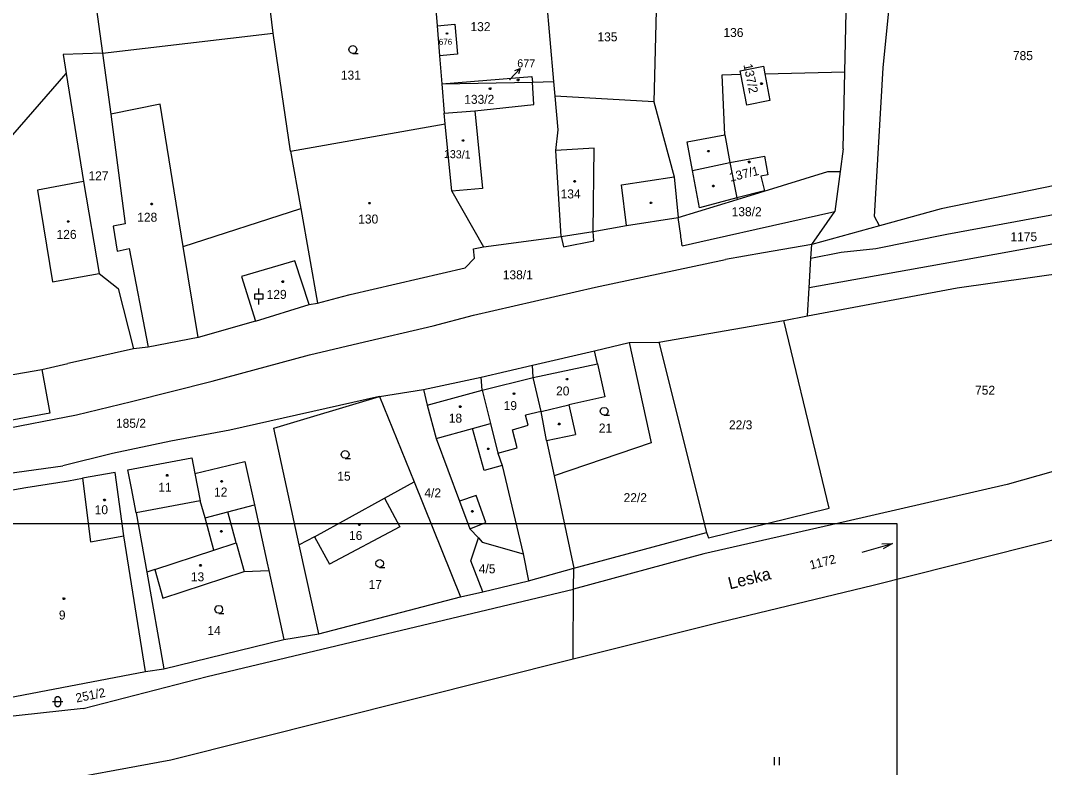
# Model space of a CAD drawing. Extents: x -812394 to -807601, y -1013097 to -1009266.
# Drawn here: x -809612.2 to -809418.3, y -1010813 to -1010671.6 of the extents above; entities that cross this region are included whole.
import ezdxf

# ---------------------------------------------------------------- set-up
doc = ezdxf.new("R2010")
doc.units = 0
for name, color, linetype in [('Default', 7, 'Continuous'), ('KN_HRANICE', 7, 'Continuous'), ('KN_KULTURY', 7, 'Continuous'), ('KN_PARCELY', 7, 'Continuous'), ('KN_SLUCKY', 7, 'Continuous'), ('LEGENDA', 7, 'Continuous')]:
    doc.layers.add(name, color=color, linetype=linetype)

# ---------------------------------------------------------------- blocks, each defined once
blk = doc.blocks.new('10292')
at = {"layer": 'Default'}
blk.add_line((0, 3), (0, 0), dxfattribs=at)
blk.add_lwpolyline([(-0.5, 2), (0, 3), (0.5, 2)], dxfattribs=at)
blk = doc.blocks.new('304')
at = {"layer": 'Default'}
blk.add_lwpolyline([(0, 0), (-0.38, 0.1), (-0.65, 0.37), (-0.75, 0.74), (-0.65, 1.11), (-0.38, 1.38), (-0.01, 1.48), (0.36, 1.38), (0.63, 1.11), (0.73, 0.73), (0.63, 0.35), (0.36, 0.08), (-0.02, -0.02), (0.98, -0.02)], dxfattribs=at)
blk = doc.blocks.new('306')
at = {"layer": 'Default'}
for p, q in [((-0.5, 1.5), (-0.5, 0)), ((0.5, 0), (0.5, 1.5))]:
    blk.add_line(p, q, dxfattribs=at)
blk = doc.blocks.new('316')
at = {"layer": 'Default'}
for points in [[(-0.5, 1.5), (-0.4, 1.79), (-0.15, 1.97), (0.16, 1.97), (0.41, 1.79), (0.51, 1.5), (0.51, 0.5), (0.41, 0.21), (0.16, 0.03), (-0.15, 0.03), (-0.4, 0.21), (-0.5, 0.5), (-0.5, 1.5)], [(-1, 1), (0.27, 1), (1, 1)]]:
    blk.add_lwpolyline(points, dxfattribs=at)
blk = doc.blocks.new('NAHRADNI_SYMBOL')
at = {"layer": 'Default'}
blk.add_lwpolyline([(0.09, 0.15), (0.18, 0), (0.09, -0.15), (-0.09, -0.15), (-0.18, 0), (-0.09, 0.15), (0.09, 0.15)], dxfattribs=at)
blk = doc.blocks.new('802')
at = {"layer": 'Default'}
blk.add_line((-3, 0), (3, 0), dxfattribs=at)
blk.add_lwpolyline([(1, 0.5), (3, 0), (1, -0.5)], dxfattribs=at)
blk = doc.blocks.new('318')
at = {"layer": 'Default'}
blk.add_line((0, 2), (0, 3), dxfattribs=at)
blk.add_lwpolyline([(0, 0), (0, 1), (-0.75, 1), (-0.75, 2), (0, 2), (0.75, 2), (0.75, 1), (0, 1)], dxfattribs=at)
blk = doc.blocks.new('402')
at = {"layer": 'Default'}
blk.add_lwpolyline([(0.09, 0.15), (0.18, 0), (0.09, -0.15), (-0.09, -0.15), (-0.18, 0), (-0.09, 0.15), (0.09, 0.15)], dxfattribs=at)

msp = doc.modelspace()

# ---------------------------------------------------------------- linework, layer by layer
at = {"layer": 'KN_HRANICE'}
for p, q in [((-809448.82, -1010680.59), (-809445.9, -1010650.77)), ((-809511.21, -1010683.19), (-809513.45, -1010657.55)), ((-809491.57, -1010658.3), (-809492.27, -1010687)), ((-809534.45, -1010658.78), (-809533.33, -1010672.61)), ((-809564.36, -1010674), (-809565.97, -1010661.03)), ((-809456.08, -1010681.32), (-809455.72, -1010664.14)), ((-809598.46, -1010664.88), (-809596.67, -1010677.83)), ((-809561.08, -1010696.34), (-809564.36, -1010674)), ((-809533.33, -1010672.61), (-809532.87, -1010678.29)), ((-809596.67, -1010677.83), (-809604.12, -1010678.05)), ((-809604.12, -1010678.05), (-809603.55, -1010681.64)), ((-809596.67, -1010677.83), (-809595.14, -1010689.36)), ((-809532.87, -1010678.29), (-809532.44, -1010683.62)), ((-809603.55, -1010681.64), (-809600.29, -1010702.1)), ((-809479.37, -1010681.9), (-809475.82, -1010681.81)), ((-809478.82, -1010693.3), (-809479.37, -1010681.9)), ((-809475.94, -1010681.16), (-809471.53, -1010680.26)), ((-809475.82, -1010681.81), (-809475.94, -1010681.16)), ((-809474.7, -1010687.64), (-809475.82, -1010681.81)), ((-809471.53, -1010680.26), (-809471.26, -1010681.7)), ((-809471.26, -1010681.7), (-809456.08, -1010681.32)), ((-809471.26, -1010681.7), (-809470.29, -1010686.8)), ((-809456.4, -1010695.91), (-809456.08, -1010681.32)), ((-809450.49, -1010708.71), (-809448.82, -1010680.59)), ((-809532.44, -1010683.62), (-809515.29, -1010683.27)), ((-809532.44, -1010683.62), (-809531.99, -1010689.19)), ((-809515.29, -1010683.27), (-809511.21, -1010683.19)), ((-809510.97, -1010685.95), (-809511.21, -1010683.19)), ((-809492.27, -1010687), (-809510.97, -1010685.95)), ((-809510.41, -1010692.32), (-809510.97, -1010685.95)), ((-809492.27, -1010687), (-809488.44, -1010701.23)), ((-809470.29, -1010686.8), (-809474.7, -1010687.64)), ((-809595.14, -1010689.36), (-809592.38, -1010710.12)), ((-809531.99, -1010689.19), (-809526.16, -1010688.74)), ((-809531.79, -1010691.19), (-809531.99, -1010689.19)), ((-809561.08, -1010696.34), (-809531.79, -1010691.19)), ((-809530.54, -1010703.91), (-809531.79, -1010691.19)), ((-809510.85, -1010696.24), (-809510.41, -1010692.32)), ((-809485.94, -1010694.61), (-809478.82, -1010693.3)), ((-809484.96, -1010700.01), (-809485.94, -1010694.61)), ((-809561.08, -1010696.34), (-809559.16, -1010707.24)), ((-809509.86, -1010712.52), (-809510.85, -1010696.24)), ((-809456.4, -1010695.91), (-809456.99, -1010700.24)), ((-809488.44, -1010701.23), (-809487.68, -1010708.94)), ((-809483.66, -1010707.09), (-809484.96, -1010700.01)), ((-809476.51, -1010705.51), (-809459.32, -1010700.23)), ((-809459.32, -1010700.23), (-809456.99, -1010700.24)), ((-809456.99, -1010700.24), (-809458, -1010707.77)), ((-809600.29, -1010702.1), (-809597.34, -1010719.54)), ((-809413.39, -1010702.26), (-809437.86, -1010707.26)), ((-809530.54, -1010703.91), (-809524.53, -1010714.47)), ((-809476.56, -1010705.21), (-809483.66, -1010707.09)), ((-809476.56, -1010705.21), (-809476.51, -1010705.51)), ((-809487.68, -1010708.94), (-809476.51, -1010705.51)), ((-809581.39, -1010714.41), (-809559.16, -1010707.24)), ((-809559.16, -1010707.24), (-809556, -1010725.11)), ((-809497.45, -1010710.44), (-809487.68, -1010708.94)), ((-809487.2, -1010712.35), (-809487.68, -1010708.94)), ((-809481.63, -1010713.11), (-809458, -1010707.77)), ((-809462.39, -1010714.03), (-809458, -1010707.77)), ((-809449.57, -1010710.49), (-809450.49, -1010708.71)), ((-809437.86, -1010707.26), (-809449.57, -1010710.49)), ((-809592.38, -1010710.12), (-809594.66, -1010710.54)), ((-809594.66, -1010710.54), (-809593.93, -1010715.27)), ((-809503.76, -1010711.54), (-809497.45, -1010710.44)), ((-809449.57, -1010710.49), (-809462.39, -1010714.03)), ((-809524.53, -1010714.47), (-809509.86, -1010712.52)), ((-809509.86, -1010712.52), (-809509.39, -1010714.47)), ((-809503.65, -1010713.32), (-809503.76, -1010711.54)), ((-809487.15, -1010712.67), (-809487.2, -1010712.35)), ((-809487.06, -1010713.28), (-809487.15, -1010712.67)), ((-809593.93, -1010715.27), (-809591.65, -1010714.79)), ((-809591.65, -1010714.79), (-809588.06, -1010733.47)), ((-809578.59, -1010731.65), (-809581.39, -1010714.41)), ((-809526.41, -1010714.85), (-809524.53, -1010714.47)), ((-809526.26, -1010716.6), (-809526.41, -1010714.85)), ((-809509.39, -1010714.47), (-809503.65, -1010713.32)), ((-809486.99, -1010713.83), (-809487.06, -1010713.28)), ((-809486.92, -1010714.3), (-809486.99, -1010713.83)), ((-809486.92, -1010714.3), (-809481.63, -1010713.11)), ((-809462.39, -1010714.03), (-809471.53, -1010715.63)), ((-809462.54, -1010716.59), (-809462.39, -1010714.03)), ((-809528.01, -1010718.45), (-809526.26, -1010716.6)), ((-809503.35, -1010722.13), (-809478.73, -1010716.9)), ((-809471.53, -1010715.63), (-809478.73, -1010716.9)), ((-809462.86, -1010722.22), (-809462.54, -1010716.59)), ((-809434.83, -1010722.26), (-809386.46, -1010715.35)), ((-809549.8, -1010723.5), (-809528.01, -1010718.45)), ((-809597.34, -1010719.54), (-809593.76, -1010722.34)), ((-809593.76, -1010722.34), (-809590.8, -1010733.81)), ((-809526.46, -1010727.38), (-809503.35, -1010722.13)), ((-809463.16, -1010727.52), (-809462.86, -1010722.22)), ((-809463.16, -1010727.52), (-809434.83, -1010722.26)), ((-809556, -1010725.11), (-809551.26, -1010723.86)), ((-809551.26, -1010723.86), (-809549.8, -1010723.5)), ((-809567.73, -1010728.55), (-809557.57, -1010725.36)), ((-809557.57, -1010725.36), (-809556, -1010725.11)), ((-809567.73, -1010728.55), (-809578.59, -1010731.65)), ((-809534.09, -1010729.46), (-809526.46, -1010727.38)), ((-809491.31, -1010732.5), (-809467.68, -1010728.42)), ((-809467.68, -1010728.42), (-809463.16, -1010727.52)), ((-809548.16, -1010732.72), (-809534.09, -1010729.46)), ((-809578.59, -1010731.65), (-809588.06, -1010733.47)), ((-809590.8, -1010733.81), (-809601.82, -1010736.22)), ((-809588.06, -1010733.47), (-809590.8, -1010733.81)), ((-809557.49, -1010734.93), (-809548.16, -1010732.72)), ((-809515.24, -1010736.89), (-809503.51, -1010734.14)), ((-809503.51, -1010734.14), (-809496.94, -1010732.6)), ((-809502.98, -1010736.65), (-809503.51, -1010734.14)), ((-809496.94, -1010732.6), (-809491.31, -1010732.5)), ((-809496.94, -1010732.6), (-809492.77, -1010751.6)), ((-809491.31, -1010732.5), (-809482.31, -1010768.54)), ((-809601.82, -1010736.22), (-809603.28, -1010736.54)), ((-809575.93, -1010739.9), (-809557.49, -1010734.93)), ((-809618.66, -1010739.51), (-809608.17, -1010737.7)), ((-809608.17, -1010737.7), (-809603.28, -1010736.54)), ((-809608.17, -1010737.7), (-809606.66, -1010745.99)), ((-809524.96, -1010739.16), (-809515.24, -1010736.89)), ((-809515.12, -1010739.21), (-809515.24, -1010736.89)), ((-809502.98, -1010736.65), (-809501.59, -1010742.84)), ((-809591.21, -1010743.76), (-809575.93, -1010739.9)), ((-809535.88, -1010741.49), (-809524.96, -1010739.16)), ((-809524.82, -1010741.63), (-809524.96, -1010739.16)), ((-809513.6, -1010745.64), (-809515.12, -1010739.21)), ((-809544.23, -1010742.79), (-809535.88, -1010741.49)), ((-809535.88, -1010741.49), (-809535.22, -1010744.44)), ((-809524.82, -1010741.63), (-809523.2, -1010747.95)), ((-809601.6, -1010746.29), (-809591.21, -1010743.76)), ((-809544.23, -1010742.79), (-809572.56, -1010749.19)), ((-809564.25, -1010748.81), (-809544.23, -1010742.79)), ((-809544.23, -1010742.79), (-809537.7, -1010758.97)), ((-809501.59, -1010742.84), (-809508.37, -1010744.41)), ((-809606.66, -1010745.99), (-809626.64, -1010749.55)), ((-809535.22, -1010744.44), (-809533.52, -1010750.77)), ((-809512.59, -1010751.13), (-809513.6, -1010745.64)), ((-809508.37, -1010744.41), (-809507.14, -1010750.01)), ((-809621.25, -1010750.05), (-809601.6, -1010746.29)), ((-809572.56, -1010749.19), (-809583.73, -1010751.27)), ((-809559.42, -1010770.87), (-809564.25, -1010748.81)), ((-809523.2, -1010747.95), (-809521.85, -1010753.55)), ((-809583.73, -1010751.27), (-809594.82, -1010753.62)), ((-809533.52, -1010750.77), (-809529.09, -1010762.64)), ((-809512.59, -1010751.13), (-809507.14, -1010750.01)), ((-809512.59, -1010751.13), (-809511.16, -1010757.85)), ((-809492.77, -1010751.6), (-809511.16, -1010757.85)), ((-809594.82, -1010753.62), (-809604.22, -1010755.92)), ((-809521.85, -1010753.55), (-809521.03, -1010755.88)), ((-809591.91, -1010756.66), (-809579.76, -1010754.43)), ((-809579.76, -1010754.43), (-809579.19, -1010757.38)), ((-809579.19, -1010757.38), (-809569.76, -1010755.12)), ((-809569.76, -1010755.12), (-809567.94, -1010763.34)), ((-809619.48, -1010758), (-809604.22, -1010755.92)), ((-809594.29, -1010757.19), (-809600.5, -1010758.29)), ((-809592.64, -1010769.19), (-809594.29, -1010757.19)), ((-809591.2, -1010760.14), (-809591.91, -1010756.66)), ((-809579.19, -1010757.38), (-809578.18, -1010762.54)), ((-809521.03, -1010755.88), (-809517.06, -1010772.62)), ((-809611.19, -1010760.06), (-809603.15, -1010758.78)), ((-809603.15, -1010758.78), (-809600.5, -1010758.29)), ((-809600.5, -1010758.29), (-809598.99, -1010770.33)), ((-809543.29, -1010762.05), (-809537.7, -1010758.97)), ((-809537.7, -1010758.97), (-809528.91, -1010780.74)), ((-809511.16, -1010757.85), (-809507.45, -1010775.29)), ((-809619.76, -1010761.5), (-809611.19, -1010760.06)), ((-809590.34, -1010764.82), (-809591.2, -1010760.14)), ((-809577.28, -1010765.78), (-809578.18, -1010762.54)), ((-809572.99, -1010764.66), (-809567.94, -1010763.34)), ((-809567.94, -1010763.34), (-809565.5, -1010774.33)), ((-809556.56, -1010769.35), (-809543.29, -1010762.05)), ((-809543.29, -1010762.05), (-809540.4, -1010767.48)), ((-809529.09, -1010762.64), (-809527.15, -1010767.85)), ((-809590.34, -1010764.82), (-809588.33, -1010776.05)), ((-809577.28, -1010765.78), (-809572.99, -1010764.66)), ((-809481.91, -1010769.54), (-809459.07, -1010763.94)), ((-809575.59, -1010771.87), (-809577.28, -1010765.78)), ((-809598.99, -1010770.33), (-809592.64, -1010769.19)), ((-809588.54, -1010794.9), (-809592.64, -1010769.19)), ((-809540.4, -1010767.48), (-809553.7, -1010774.56)), ((-809527.15, -1010767.85), (-809525.51, -1010769.54)), ((-809507.45, -1010775.29), (-809482.31, -1010768.54)), ((-809482.31, -1010768.54), (-809481.91, -1010769.54)), ((-809450.75, -1010778.5), (-809413.92, -1010769.26)), ((-809556.56, -1010769.35), (-809559.42, -1010770.87)), ((-809555.73, -1010787.74), (-809559.42, -1010770.87)), ((-809556.56, -1010769.35), (-809553.7, -1010774.56)), ((-809526.96, -1010773.94), (-809525.51, -1010769.54)), ((-809525.51, -1010769.54), (-809524.78, -1010770.4)), ((-809524.78, -1010770.4), (-809517.06, -1010772.62)), ((-809586.77, -1010775.53), (-809575.59, -1010771.87)), ((-809517.06, -1010772.62), (-809516.02, -1010777.68)), ((-809565.5, -1010774.33), (-809565.19, -1010775.74)), ((-809524.66, -1010779.77), (-809526.96, -1010773.94)), ((-809586.77, -1010775.53), (-809588.33, -1010776.05)), ((-809588.33, -1010776.05), (-809585.11, -1010794.39)), ((-809586.77, -1010775.53), (-809585.25, -1010781)), ((-809585.25, -1010781), (-809569.85, -1010775.96)), ((-809569.85, -1010775.96), (-809565.19, -1010775.74)), ((-809565.19, -1010775.74), (-809562.33, -1010788.78)), ((-809516.02, -1010777.68), (-809507.45, -1010775.29)), ((-809507.48, -1010779.27), (-809507.45, -1010775.29)), ((-809524.66, -1010779.77), (-809516.02, -1010777.68)), ((-809479.79, -1010785.54), (-809450.75, -1010778.5)), ((-809576.87, -1010795.8), (-809507.48, -1010779.27)), ((-809555.73, -1010787.74), (-809528.91, -1010780.74)), ((-809528.91, -1010780.74), (-809524.66, -1010779.77)), ((-809507.51, -1010783.2), (-809507.48, -1010779.27)), ((-809507.54, -1010787.61), (-809507.51, -1010783.2)), ((-809507.57, -1010792.49), (-809479.79, -1010785.54)), ((-809562.33, -1010788.78), (-809555.73, -1010787.74)), ((-809507.57, -1010792.49), (-809507.54, -1010787.61)), ((-809585.11, -1010794.39), (-809562.33, -1010788.78)), ((-809583.77, -1010811.56), (-809507.57, -1010792.49)), ((-809588.54, -1010794.9), (-809585.11, -1010794.39)), ((-809615.96, -1010800.09), (-809588.54, -1010794.9)), ((-809600.38, -1010801.89), (-809576.87, -1010795.8)), ((-809600.38, -1010801.89), (-809643.49, -1010806.47)), ((-809609.07, -1010816.23), (-809583.77, -1010811.56))]:
    msp.add_line(p, q, dxfattribs=at)
for points in [[(-809533.33, -1010672.61), (-809529.94, -1010672.33), (-809529.46, -1010677.99), (-809532.87, -1010678.29)], [(-809623.13, -1010728.35), (-809625.78, -1010708.61), (-809623.83, -1010704.87), (-809603.55, -1010681.64)], [(-809532.44, -1010683.62), (-809515.36, -1010682.23), (-809515.29, -1010683.27)], [(-809526.16, -1010688.74), (-809514.99, -1010687.55), (-809515.29, -1010683.27)], [(-809386.86, -1010717.18), (-809390.64, -1010734.74), (-809392.82, -1010743.13), (-809395.75, -1010747.43), (-809400.98, -1010751.89), (-809410.38, -1010755.21), (-809425.36, -1010759.45), (-809455.87, -1010766.45), (-809482.83, -1010772.6), (-809507.48, -1010779.27)], [(-809459.07, -1010763.94), (-809461.16, -1010755.31), (-809467.68, -1010728.42)]]:
    msp.add_lwpolyline(points, dxfattribs=at)
at = {"layer": 'KN_SLUCKY'}
for p, q in [((-809596.67, -1010677.83), (-809564.36, -1010674)), ((-809585.78, -1010687.46), (-809595.14, -1010689.36)), ((-809581.39, -1010714.41), (-809585.78, -1010687.46)), ((-809526.16, -1010688.74), (-809524.76, -1010703.42)), ((-809478.82, -1010693.3), (-809477.86, -1010698.52)), ((-809503.61, -1010695.79), (-809510.85, -1010696.24)), ((-809503.76, -1010711.54), (-809503.61, -1010695.79)), ((-809477.86, -1010698.52), (-809471.32, -1010697.32)), ((-809471.32, -1010697.32), (-809470.68, -1010700.85)), ((-809484.96, -1010700.01), (-809477.86, -1010698.52)), ((-809477.86, -1010698.52), (-809476.56, -1010705.21)), ((-809498.4, -1010702.75), (-809488.44, -1010701.23)), ((-809470.68, -1010700.85), (-809472.02, -1010701.1)), ((-809472.02, -1010701.1), (-809471.31, -1010703.88)), ((-809600.29, -1010702.1), (-809609, -1010703.76)), ((-809497.45, -1010710.44), (-809498.4, -1010702.75)), ((-809609, -1010703.76), (-809606.14, -1010721.1)), ((-809524.76, -1010703.42), (-809530.54, -1010703.91)), ((-809471.31, -1010703.88), (-809476.56, -1010705.21)), ((-809509.86, -1010712.52), (-809503.76, -1010711.54)), ((-809560.3, -1010717.14), (-809570.39, -1010720.06)), ((-809557.57, -1010725.36), (-809560.3, -1010717.14)), ((-809606.14, -1010721.1), (-809597.34, -1010719.54)), ((-809570.39, -1010720.06), (-809567.73, -1010728.55)), ((-809515.12, -1010739.21), (-809502.98, -1010736.65)), ((-809524.82, -1010741.63), (-809515.12, -1010739.21)), ((-809535.22, -1010744.44), (-809524.82, -1010741.63)), ((-809513.6, -1010745.64), (-809516.56, -1010746.35)), ((-809513.6, -1010745.64), (-809508.37, -1010744.41)), ((-809516.09, -1010748.24), (-809516.56, -1010746.35)), ((-809533.52, -1010750.77), (-809526.63, -1010748.89)), ((-809526.63, -1010748.89), (-809523.2, -1010747.95)), ((-809524.42, -1010756.83), (-809526.63, -1010748.89)), ((-809519.06, -1010749.09), (-809516.09, -1010748.24)), ((-809518.14, -1010752.55), (-809519.06, -1010749.09)), ((-809521.85, -1010753.55), (-809518.14, -1010752.55)), ((-809521.03, -1010755.88), (-809524.42, -1010756.83)), ((-809525.94, -1010761.52), (-809529.09, -1010762.64)), ((-809524.07, -1010766.63), (-809525.94, -1010761.52)), ((-809578.18, -1010762.54), (-809590.34, -1010764.82)), ((-809571.37, -1010770.49), (-809572.99, -1010764.66)), ((-809527.15, -1010767.85), (-809524.07, -1010766.63)), ((-809575.59, -1010771.87), (-809571.37, -1010770.49)), ((-809571.37, -1010770.49), (-809569.85, -1010775.96))]:
    msp.add_line(p, q, dxfattribs=at)
for points in [[(-809462.54, -1010716.59), (-809456.78, -1010715.47), (-809450.24, -1010714.77), (-809436.78, -1010712.1), (-809413.21, -1010707.7), (-809386.06, -1010702.58)], [(-809385.19, -1010708.29), (-809412.36, -1010713.13), (-809435.74, -1010717.37), (-809462.86, -1010722.22)]]:
    msp.add_lwpolyline(points, dxfattribs=at)
at = {"layer": 'LEGENDA'}
msp.add_lwpolyline([(-810040.19, -1011186.89), (-809446.19, -1011186.89), (-809446.19, -1010766.89), (-810040.19, -1010766.89)], close=True, dxfattribs=at)

# ---------------------------------------------------------------- block references
at = {"layer": 'KN_KULTURY'}
for name, p in [('402', (-809531.46, -1010674.08)), ('304', (-809549.27, -1010677.86)), ('402', (-809517.99, -1010682.9)), ('402', (-809471.88, -1010683.59)), ('402', (-809523.3, -1010684.54)), ('402', (-809528.4, -1010694.35)), ('402', (-809481.95, -1010696.36)), ('402', (-809474.22, -1010698.43)), ('402', (-809507.27, -1010702.09)), ('402', (-809481.01, -1010702.97)), ('402', (-809587.39, -1010706.38)), ('NAHRADNI_SYMBOL', (-809546.13, -1010706.21)), ('402', (-809492.83, -1010706.14)), ('402', (-809603.18, -1010709.67)), ('318', (-809567.07, -1010725.36)), ('402', (-809562.55, -1010721.09)), ('402', (-809508.71, -1010739.53)), ('402', (-809518.76, -1010742.26)), ('402', (-809528.95, -1010744.75)), ('304', (-809501.69, -1010746.34)), ('402', (-809510.19, -1010747.99)), ('304', (-809550.72, -1010754.51)), ('402', (-809523.65, -1010752.72)), ('402', (-809584.45, -1010757.72)), ('NAHRADNI_SYMBOL', (-809574.13, -1010758.87)), ('402', (-809596.3, -1010762.41)), ('402', (-809526.65, -1010764.55)), ('402', (-809548.06, -1010767.1)), ('402', (-809574.2, -1010768.35)), ('402', (-809578.14, -1010774.75)), ('304', (-809544.19, -1010775.16)), ('NAHRADNI_SYMBOL', (-809604.01, -1010781.1)), ('304', (-809574.67, -1010783.84)), ('316', (-809605.18, -1010801.57)), ('306', (-809469.01, -1010812.57))]:
    msp.add_blockref(name, p, dxfattribs=at)
at = {"layer": 'KN_KULTURY', "rotation": 15.527156}
msp.add_blockref('802', (-809449.95, -1010771.45), dxfattribs=at)
at = {"layer": 'KN_PARCELY', "rotation": -43.72729700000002}
msp.add_blockref('10292', (-809519.64, -1010682.85), dxfattribs=at)

# ---------------------------------------------------------------- texts
at = {"layer": 'KN_PARCELY'}
for s, height, p in [('132', 1.7, (-809527.01, -1010673.64)), ('135', 1.7, (-809502.96, -1010675.57)), ('136', 1.7, (-809479.1, -1010674.75)), ('785', 1.7, (-809424.28, -1010679.13)), ('131', 1.7, (-809551.56, -1010682.81)), ('677', 0.1, (-809519.62, -1010682.95)), ('133/2', 1.7, (-809528.19, -1010687.4)), ('127', 1.7, (-809599.35, -1010701.88)), ('134', 1.7, (-809509.94, -1010705.31)), ('138/2', 1.7, (-809477.55, -1010708.67)), ('128', 1.7, (-809590.12, -1010709.72)), ('130', 1.7, (-809548.27, -1010710.06)), ('126', 1.7, (-809605.4, -1010712.97)), ('1175', 1.7, (-809424.75, -1010713.41)), ('138/1', 1.7, (-809520.89, -1010720.62)), ('129', 1.7, (-809565.61, -1010724.33)), ('20', 1.7, (-809510.8, -1010742.61)), ('752', 1.7, (-809431.45, -1010742.46)), ('19', 1.7, (-809520.73, -1010745.38)), ('185/2', 1.7, (-809594.15, -1010748.73)), ('18', 1.7, (-809531.12, -1010747.76)), ('21', 1.7, (-809502.71, -1010749.63)), ('22/3', 1.7, (-809478.05, -1010749.02)), ('15', 1.7, (-809552.23, -1010758.74)), ('11', 1.7, (-809586.13, -1010760.85)), ('12', 1.7, (-809575.57, -1010761.74)), ('4/2', 1.7, (-809535.74, -1010761.91)), ('22/2', 1.7, (-809498.01, -1010762.81)), ('10', 1.7, (-809598.18, -1010765.09)), ('16', 1.7, (-809550.01, -1010769.97)), ('4/5', 1.7, (-809525.44, -1010776.27)), ('13', 1.7, (-809579.96, -1010777.79)), ('17', 1.7, (-809546.3, -1010779.25)), ('9', 1.7, (-809604.96, -1010785.03)), ('14', 1.7, (-809576.84, -1010787.98))]:
    msp.add_text(s, height=height, dxfattribs=at).set_placement(p)
for s, height, rotation, p in [('676', 1.14, 0.401, (-809533.01, -1010676.24)), ('677', 1.52, 359.015, (-809518.16, -1010680.47)), ('137/2', 1.7, 281.838, (-809475.33, -1010680)), ('133/1', 1.52, 358.672, (-809532.07, -1010697.65)), ('137/1', 1.7, 13.407, (-809477.79, -1010702.15)), ('1172', 1.7, 14.324, (-809462.56, -1010775.58)), ('Leska', 2.3, 13.808, (-809477.9, -1010779.33)), ('251/2', 1.7, 11.574, (-809601.6, -1010800.76))]:
    msp.add_text(s, height=height, rotation=rotation, dxfattribs=at).set_placement(p)

doc.saveas('drawing.dxf')
